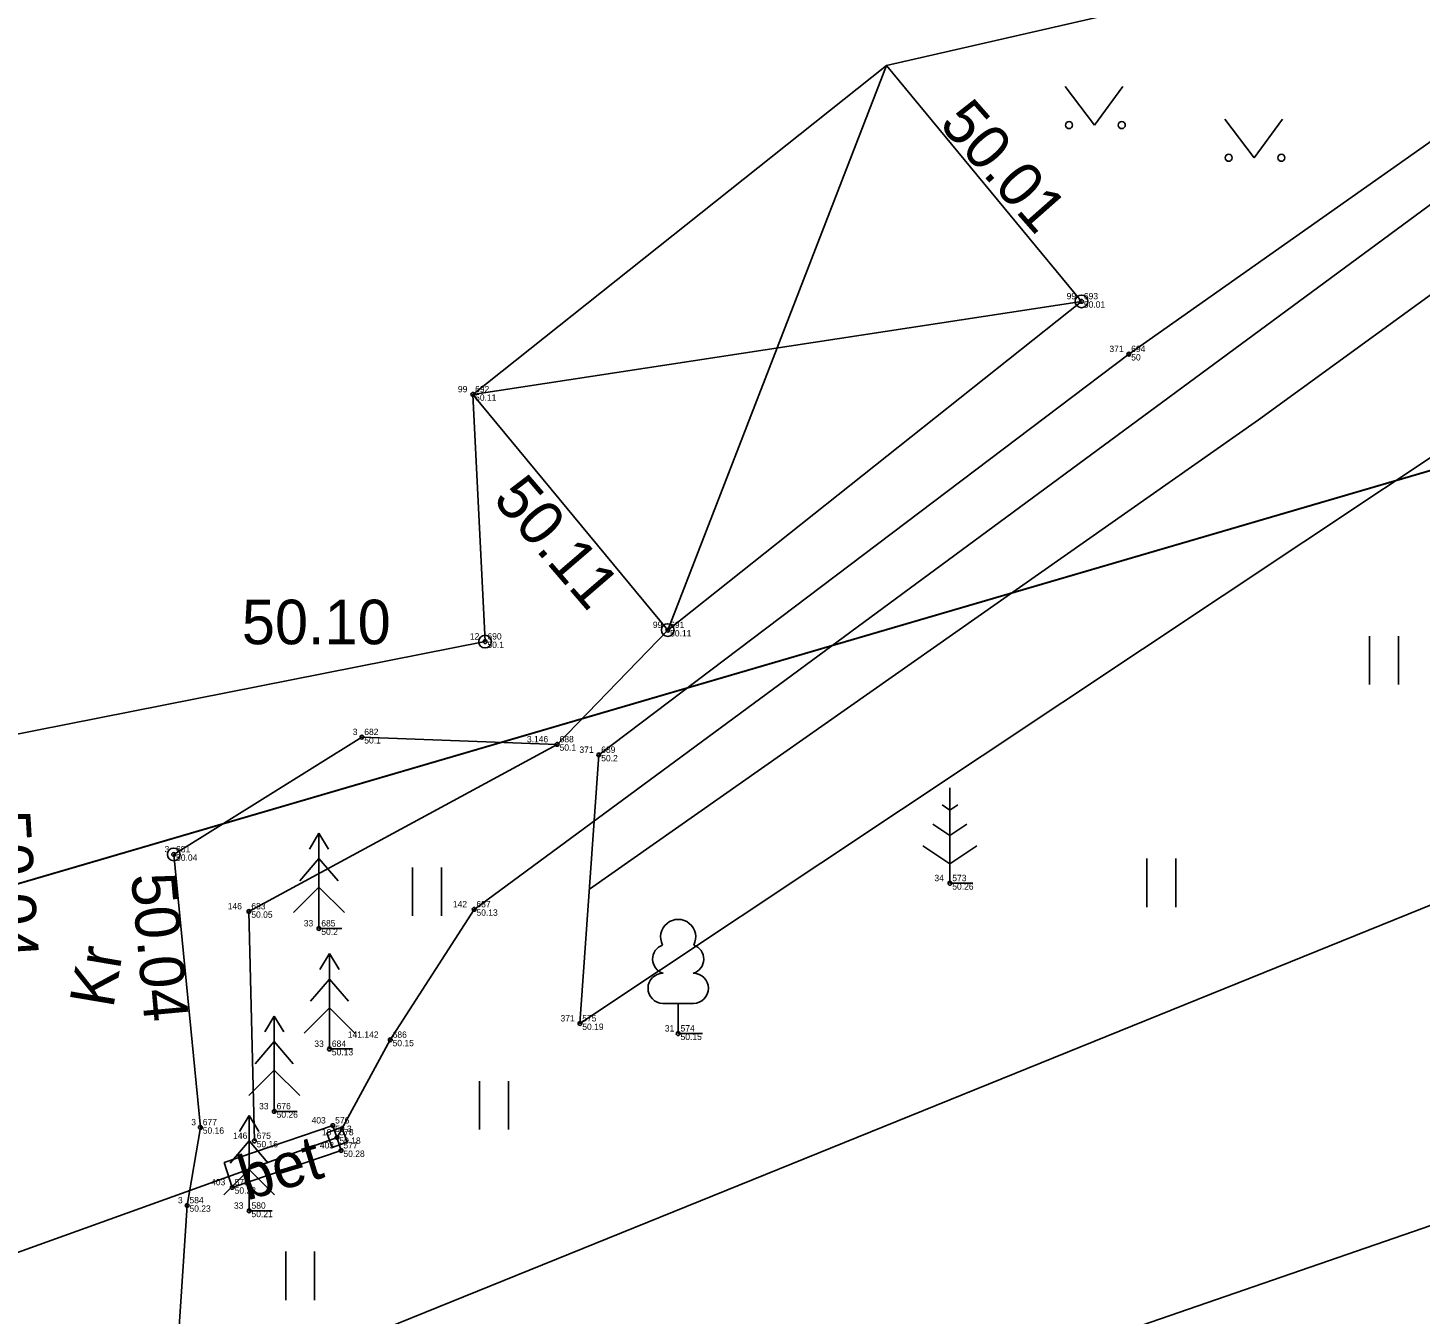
# Model space of a CAD drawing. Extents: x 543497 to 552146, y 6567125 to 6579845.
# Drawn here: x 546062.67 to 546084.57, y 6577707.71 to 6577727.95 of the extents above; entities that cross this region are included whole.
import ezdxf

# ---------------------------------------------------------------- set-up
doc = ezdxf.new("R2010")
doc.units = 0
for name, color, linetype in [('xref_Kangru tee 1_geodeesia$0$AED', 7, 'Continuous'), ('xref_Kangru tee 1_geodeesia$0$HALJASTUS', 7, 'Continuous'), ('xref_Kangru tee 1_geodeesia$0$HOONE', 7, 'Continuous'), ('xref_Kangru tee 1_geodeesia$0$HOONEDET', 7, 'Continuous'), ('xref_Kangru tee 1_geodeesia$0$korgus-EH2000', 7, 'Continuous'), ('xref_Kangru tee 1_geodeesia$0$mootkood', 7, 'Continuous'), ('xref_Kangru tee 1_geodeesia$0$MOOTKORG-eh2000', 7, 'Continuous'), ('xref_Kangru tee 1_geodeesia$0$mootmpunkt', 7, 'Continuous'), ('xref_Kangru tee 1_geodeesia$0$MOOTNR', 7, 'Continuous'), ('xref_Kangru tee 1_geodeesia$0$MOOTPIIR', 7, 'Continuous'), ('xref_Kangru tee 1_geodeesia$0$PIIR', 7, 'Continuous'), ('xref_Kangru tee 1_geodeesia$0$PUU', 7, 'Continuous'), ('xref_Kangru tee 1_geodeesia$0$RAJATIS', 7, 'Continuous'), ('xref_Kangru tee 1_geodeesia$0$TEE', 7, 'Continuous')]:
    doc.layers.add(name, color=color, linetype=linetype)

# ---------------------------------------------------------------- blocks, each defined once
blk = doc.blocks.new('xref_Kangru tee 1_geodeesia$0$mand1')
for p, q in [((0, 3), (0, 0)), ((0, 2.3), (-0.249, 2.466)), ((0.249, 2.466), (0, 2.3)), ((0, 1.5), (-0.533, 1.855)), ((0.533, 1.855), (0, 1.5)), ((-0.849, 1.179), (0, 0.613)), ((0, 0.613), (0.849, 1.179)), ((0.72, 0), (0, 0))]:
    blk.add_line(p, q)
blk = doc.blocks.new('xref_Kangru tee 1_geodeesia$0$LEHTP1')
for p, q in [((0.48, 0.95), (-0.48, 0.95)), ((0, 0), (0, 0.95)), ((0.76, 0), (0, 0))]:
    blk.add_line(p, q)
for centre, radius, start, end in [((0, 3.04), 0.554, 332.5799, 207.4201), ((-0.34, 2.345), 0.465, 109.0217, 253.1415), ((0.34, 2.345), 0.465, 286.8508, 70.9859), ((-0.475, 1.425), 0.475, 90.0016, 269.3953), ((0.475, 1.425), 0.475, 270.6047, 89.9984)]:
    blk.add_arc(centre, radius, start, end)
blk = doc.blocks.new('xref_Kangru tee 1_geodeesia$0$varpos')
for p, q in [((-0.25, 0.25), (-0.25, -0.25)), ((-0.25, 0.25), (0.25, 0.25)), ((0.25, 0.25), (0.25, -0.25)), ((-0.25, -0.25), (0.25, -0.25))]:
    blk.add_line(p, q)
blk = doc.blocks.new('xref_Kangru tee 1_geodeesia$0$KUUSK1')
for p, q in [((0, 3), (-0.3, 2.5)), ((0.3, 2.5), (0, 3)), ((0, 3), (0, 0)), ((0, 2.2), (-0.6, 1.5)), ((0.6, 1.5), (0, 2.2)), ((0, 1.3), (-0.8, 0.5)), ((0.8, 0.5), (0, 1.3)), ((0.72, 0), (0, 0))]:
    blk.add_line(p, q)
blk = doc.blocks.new('xref_Kangru tee 1_geodeesia$0$hein')
for p, q in [((-0.455, 0.761), (-0.455, -0.761)), ((0.455, 0.761), (0.455, -0.761))]:
    blk.add_line(p, q)
blk = doc.blocks.new('xref_Kangru tee 1_geodeesia$0$MURU')
for p, q in [((-0.927, 1.213), (0, 0)), ((0, 0), (0.891, 1.213))]:
    blk.add_line(p, q)
for centre in [(-0.802, 0), (0.856, 0)]:
    blk.add_circle(centre, 0.11)

msp = doc.modelspace()

# ---------------------------------------------------------------- linework, layer by layer
at = {"layer": 'xref_Kangru tee 1_geodeesia$0$AED'}
for points in [[(546068.367, 6577712.029), (546069.686, 6577714.082), (546091.653, 6577730.279)], [(546066.229, 6577710.439), (546066.144, 6577714.05), (546070.994, 6577716.678)], [(546067.53, 6577710.494), (546068.367, 6577712.029)], [(546067.53, 6577710.494), (546061.841, 6577708.446)]]:
    msp.add_lwpolyline(points, dxfattribs=at)
at = {"layer": 'xref_Kangru tee 1_geodeesia$0$HALJASTUS'}
for points in [[(546091.362, 6577730.835), (546095.124, 6577729.047), (546086.53, 6577722.387), (546071.351, 6577712.286), (546071.649, 6577716.512), (546079.987, 6577722.818), (546091.362, 6577730.835)], [(546071.5, 6577714.399), (546082.027, 6577721.783), (546093.243, 6577729.941)]]:
    msp.add_lwpolyline(points, dxfattribs=at)
at = {"layer": 'xref_Kangru tee 1_geodeesia$0$HOONE'}
msp.add_lwpolyline([(546079.242, 6577723.648), (546072.733, 6577718.476), (546069.665, 6577722.185), (546076.174, 6577727.357)], close=True, dxfattribs=at)
at = {"layer": 'xref_Kangru tee 1_geodeesia$0$HOONEDET'}
for p, q in [((546076.174, 6577727.357), (546072.733, 6577718.476)), ((546069.665, 6577722.185), (546079.242, 6577723.648))]:
    msp.add_line(p, q, dxfattribs=at)
at = {"layer": 'xref_Kangru tee 1_geodeesia$0$korgus-EH2000'}
for centre in [(546079.242, 6577723.648), (546072.733, 6577718.476), (546069.859, 6577718.295), (546064.96, 6577714.947)]:
    msp.add_circle(centre, 0.1, dxfattribs=at)
at = {"layer": 'xref_Kangru tee 1_geodeesia$0$mootmpunkt'}
for centre in [(546079.242, 6577723.648), (546079.987, 6577722.818), (546069.665, 6577722.185), (546072.733, 6577718.476), (546069.859, 6577718.295), (546067.921, 6577716.792), (546070.994, 6577716.678), (546071.649, 6577716.512), (546064.96, 6577714.947), (546077.172, 6577714.493), (546066.144, 6577714.05), (546069.686, 6577714.082), (546067.245, 6577713.781), (546071.351, 6577712.286), (546072.897, 6577712.128), (546068.367, 6577712.029), (546067.411, 6577711.886), (546066.542, 6577710.904), (546065.38, 6577710.653), (546067.463, 6577710.681), (546066.229, 6577710.439), (546067.53, 6577710.494), (546067.593, 6577710.288), (546065.882, 6577709.709), (546065.171, 6577709.425), (546066.147, 6577709.34)]:
    msp.add_circle(centre, 0.03, dxfattribs=at)
at = {"layer": 'xref_Kangru tee 1_geodeesia$0$MOOTPIIR'}
msp.add_lwpolyline([(546091.362, 6577730.835), (546076.174, 6577727.357), (546069.665, 6577722.185), (546069.859, 6577718.295), (546059.732, 6577716.292), (546047.281, 6577712.138), (546039.381, 6577710.647), (546032.006, 6577709.907), (546022.782, 6577705.611), (546019.535, 6577705.044), (546019.82, 6577703.764), (546018.234, 6577702.863), (546014.32, 6577701.586), (545991.87, 6577693.345), (545969.52, 6577687.243)], dxfattribs=at)
at = {"layer": 'xref_Kangru tee 1_geodeesia$0$PIIR'}
for points in [[(545983.53, 6577775.51), (546081.11, 6577806.12), (546096.86, 6577764.18), (546079.41, 6577756.98), (546054.12, 6577754.83), (546055.48, 6577740.79), (546080.65, 6577742.83), (546099.69, 6577747.34), (546110.26, 6577728.46), (545969.55, 6577687.28), (545983.53, 6577775.51)], [(545526.72, 6577483.94), (545567.61, 6577503.92), (545600.27, 6577519.26), (545639.76, 6577537.43), (545673.8, 6577552.72), (545712.72, 6577569.73), (545743.83, 6577582.87), (545764.02, 6577591.24), (545805.47, 6577607.21), (545907.89, 6577644.25), (545925.88, 6577650.4), (545918.84, 6577672.45), (545921.7, 6577673.29), (545969.55, 6577687.28), (546110.26, 6577728.46), (546113.86, 6577718.6), (546117.94, 6577707.48), (546328.8, 6577761.79)]]:
    msp.add_lwpolyline(points, dxfattribs=at)
at = {"layer": 'xref_Kangru tee 1_geodeesia$0$RAJATIS'}
msp.add_lwpolyline([(546065.752, 6577710.102), (546065.882, 6577709.709), (546067.593, 6577710.288), (546067.463, 6577710.681)], close=True, dxfattribs=at)
at = {"layer": 'xref_Kangru tee 1_geodeesia$0$TEE'}
msp.add_lwpolyline([(545971.433, 6577672.366), (545997.276, 6577680.49), (546019.075, 6577687.637), (546046.227, 6577696.261), (546050.233, 6577697.38), (546060.833, 6577699.813), (546062.092, 6577700.466), (546063.421, 6577702.15), (546066.8, 6577702.917), (546090.631, 6577711.146), (546112.837, 6577718.304), (546121.35, 6577721.07), (546120.4, 6577725.737), (546111.41, 6577723.208), (546088.914, 6577715.843), (546065.816, 6577706.486), (546065.244, 6577706.703), (546065.037, 6577707.357), (546065.171, 6577709.425), (546065.38, 6577710.653), (546064.96, 6577714.947), (546067.921, 6577716.792), (546070.994, 6577716.678), (546072.733, 6577718.476)], dxfattribs=at)

# ---------------------------------------------------------------- block references
at = {"layer": 'xref_Kangru tee 1_geodeesia$0$AED', "xscale": 0.5000000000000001, "yscale": 0.4999999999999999, "rotation": -160.2014802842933}
msp.add_blockref('xref_Kangru tee 1_geodeesia$0$varpos', (546067.53, 6577710.494), dxfattribs=at)
at = {"layer": 'xref_Kangru tee 1_geodeesia$0$HALJASTUS', "xscale": 0.5, "yscale": 0.5}
for name, p in [('xref_Kangru tee 1_geodeesia$0$MURU', (546079.448, 6577726.421)), ('xref_Kangru tee 1_geodeesia$0$MURU', (546081.959, 6577725.907)), ('xref_Kangru tee 1_geodeesia$0$hein', (546084, 6577718)), ('xref_Kangru tee 1_geodeesia$0$hein', (546080.5, 6577714.5)), ('xref_Kangru tee 1_geodeesia$0$hein', (546068.947, 6577714.359)), ('xref_Kangru tee 1_geodeesia$0$hein', (546070, 6577711)), ('xref_Kangru tee 1_geodeesia$0$hein', (546066.949, 6577708.317))]:
    msp.add_blockref(name, p, dxfattribs=at)
at = {"layer": 'xref_Kangru tee 1_geodeesia$0$PUU', "xscale": 0.5, "yscale": 0.5}
for name, p in [('xref_Kangru tee 1_geodeesia$0$mand1', (546077.172, 6577714.493)), ('xref_Kangru tee 1_geodeesia$0$KUUSK1', (546067.245, 6577713.781)), ('xref_Kangru tee 1_geodeesia$0$LEHTP1', (546072.897, 6577712.128)), ('xref_Kangru tee 1_geodeesia$0$KUUSK1', (546067.411, 6577711.886)), ('xref_Kangru tee 1_geodeesia$0$KUUSK1', (546066.542, 6577710.904)), ('xref_Kangru tee 1_geodeesia$0$KUUSK1', (546066.147, 6577709.34))]:
    msp.add_blockref(name, p, dxfattribs=at)

# ---------------------------------------------------------------- texts
at = {"layer": 'xref_Kangru tee 1_geodeesia$0$korgus-EH2000'}
for s, rotation, p in [(' 50.01 ', 311.4338, (546076.813, 6577726.624)), (' 50.11 ', 310.7007, (546069.794, 6577720.724)), (' 50.04 ', 273.4942, (546061.985, 6577715.88)), (' 50.04 ', 275.2774, (546064.263, 6577714.883))]:
    msp.add_text(s, height=0.7, rotation=rotation, dxfattribs=at).set_placement(p)
msp.add_text(' 50.10 ', height=0.7, dxfattribs=at).set_placement((546065.772, 6577718.254))
at = {"layer": 'xref_Kangru tee 1_geodeesia$0$mootkood'}
for s, p in [(' 99', (546078.971, 6577723.681)), (' 371', (546079.644, 6577722.851)), (' 99', (546069.394, 6577722.218)), (' 99', (546072.462, 6577718.509)), (' 12', (546069.583, 6577718.328)), (' 3', (546067.74, 6577716.825)), (' 3.146', (546070.48, 6577716.711)), (' 371', (546071.306, 6577716.545)), (' 3', (546064.779, 6577714.98)), (' 34', (546076.891, 6577714.526)), (' 146', (546065.773, 6577714.083)), (' 142', (546069.315, 6577714.115)), (' 33', (546066.969, 6577713.814)), (' 371', (546071.008, 6577712.319)), (' 141.142', (546067.662, 6577712.062)), (' 31', (546072.649, 6577712.161)), (' 33', (546067.135, 6577711.919)), (' 33', (546066.266, 6577710.937)), (' 3', (546065.199, 6577710.686)), (' 403', (546067.092, 6577710.714)), (' 10', (546067.254, 6577710.527)), (' 146', (546065.858, 6577710.472)), (' 403', (546067.222, 6577710.321)), (' 403', (546065.511, 6577709.742)), (' 3', (546064.99, 6577709.458)), (' 33', (546065.871, 6577709.373))]:
    msp.add_text(s, height=0.1, dxfattribs=at).set_placement(p)
at = {"layer": 'xref_Kangru tee 1_geodeesia$0$MOOTKORG-eh2000'}
for s, p in [(' 50.01', (546079.242, 6577723.548)), (' 50', (546079.987, 6577722.718)), (' 50.11', (546069.665, 6577722.085)), (' 50.1', (546069.859, 6577718.195)), (' 50.11', (546072.733, 6577718.376)), (' 50.1', (546067.921, 6577716.692)), (' 50.1', (546070.994, 6577716.578)), (' 50.2', (546071.649, 6577716.412)), (' 50.04', (546064.96, 6577714.847)), (' 50.26', (546077.172, 6577714.393)), (' 50.05', (546066.144, 6577713.95)), (' 50.13', (546069.686, 6577713.982)), (' 50.2', (546067.245, 6577713.681)), (' 50.19', (546071.351, 6577712.186)), (' 50.15', (546068.367, 6577711.929)), (' 50.15', (546072.897, 6577712.028)), (' 50.13', (546067.411, 6577711.786)), (' 50.26', (546066.542, 6577710.804)), (' 50.16', (546065.38, 6577710.553)), (' 50.3', (546067.463, 6577710.581)), (' 50.16', (546066.229, 6577710.339)), (' 50.18', (546067.53, 6577710.394)), (' 50.28', (546067.593, 6577710.188)), (' 50.28', (546065.882, 6577709.609)), (' 50.23', (546065.171, 6577709.325)), (' 50.21', (546066.147, 6577709.24))]:
    msp.add_text(s, height=0.1, dxfattribs=at).set_placement(p)
at = {"layer": 'xref_Kangru tee 1_geodeesia$0$MOOTNR'}
for s, p in [(' 693', (546079.242, 6577723.681)), (' 694', (546079.987, 6577722.851)), (' 692', (546069.665, 6577722.218)), (' 691', (546072.733, 6577718.509)), (' 690', (546069.859, 6577718.328)), (' 682', (546067.921, 6577716.825)), (' 688', (546070.994, 6577716.711)), (' 689', (546071.649, 6577716.545)), (' 681', (546064.96, 6577714.98)), (' 573', (546077.172, 6577714.526)), (' 683', (546066.144, 6577714.083)), (' 687', (546069.686, 6577714.115)), (' 685', (546067.245, 6577713.814)), (' 575', (546071.351, 6577712.319)), (' 686', (546068.367, 6577712.062)), (' 574', (546072.897, 6577712.161)), (' 684', (546067.411, 6577711.919)), (' 676', (546066.542, 6577710.937)), (' 677', (546065.38, 6577710.686)), (' 576', (546067.463, 6577710.714)), (' 578', (546067.53, 6577710.527)), (' 675', (546066.229, 6577710.472)), (' 577', (546067.593, 6577710.321)), (' 579', (546065.882, 6577709.742)), (' 584', (546065.171, 6577709.458)), (' 580', (546066.147, 6577709.373))]:
    msp.add_text(s, height=0.1, dxfattribs=at).set_placement(p)
at = {"layer": 'xref_Kangru tee 1_geodeesia$0$RAJATIS'}
msp.add_text('bet', height=0.7, rotation=16.9299, dxfattribs=at).set_placement((546066.109, 6577709.496))
at = {"layer": 'xref_Kangru tee 1_geodeesia$0$TEE'}
msp.add_text('Kr', height=0.7, rotation=80.387, dxfattribs=at).set_placement((546064.008, 6577712.513))

doc.saveas('drawing.dxf')
